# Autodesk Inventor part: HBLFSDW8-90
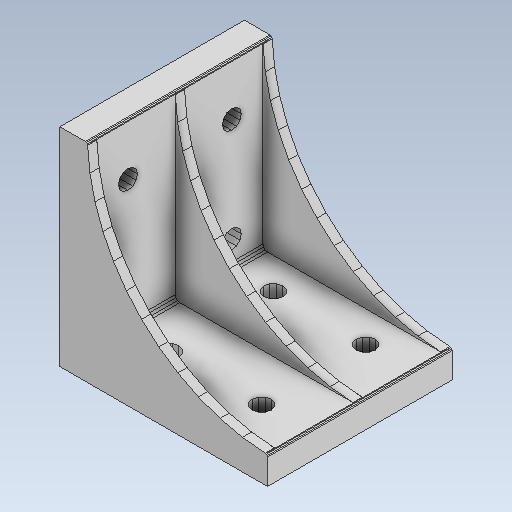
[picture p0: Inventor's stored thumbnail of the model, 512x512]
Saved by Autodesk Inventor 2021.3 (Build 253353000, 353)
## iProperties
Created: 2022-02
Part Number: HBLFSDW8-90
Material: 一般
Document SubType Name: Modeling
Designer: kengo
Density: 1 g/cm^3
Appearance: 既定
Author: kengo
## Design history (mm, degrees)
feature "HBLFSDW8-90"
node "ソリッド1"
